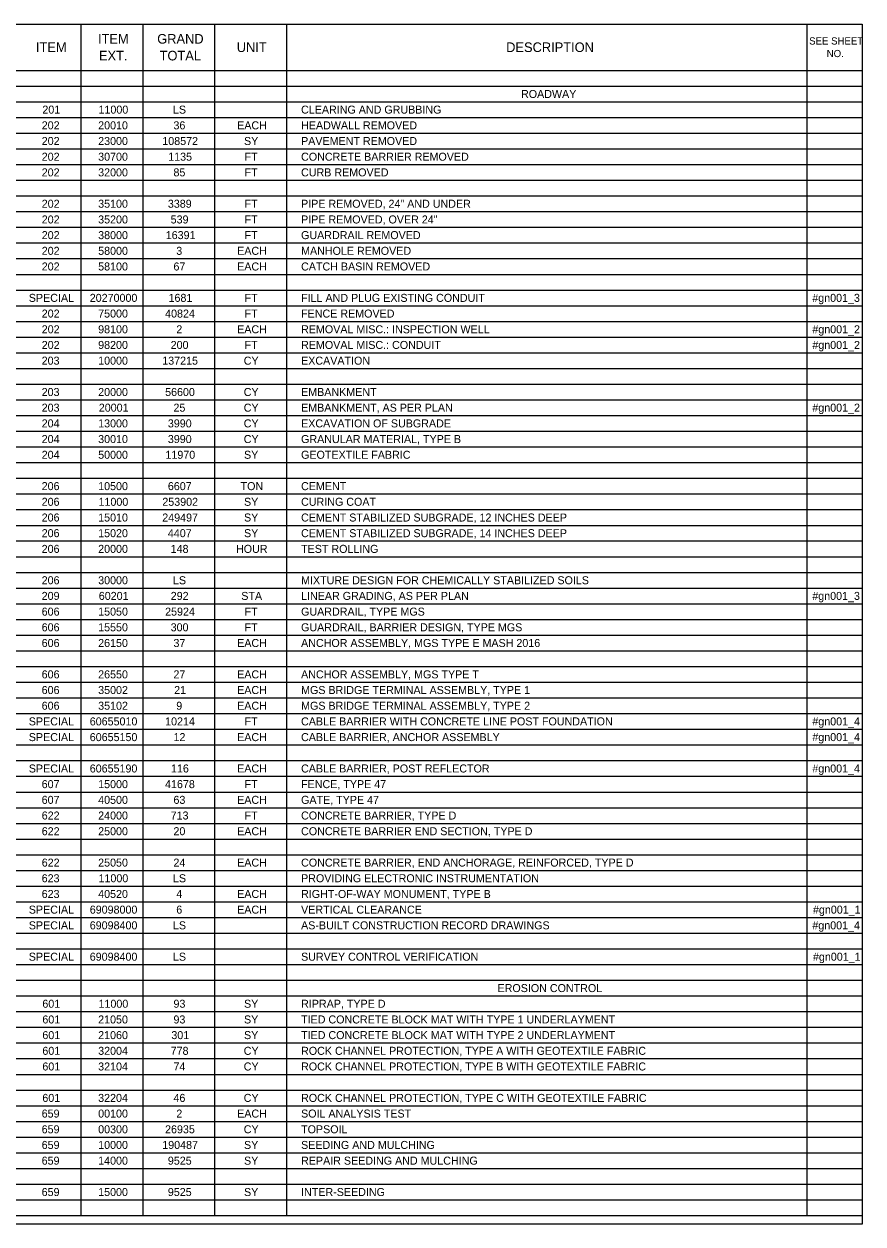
# Model space of a CAD drawing. Extents: x -542 to 295, y -281 to 32.
# Drawn here: x -400.52 to -385.84, y -10.59 to 10.41 of the extents above; entities that cross this region are included whole.
import ezdxf

# ---------------------------------------------------------------- set-up
doc = ezdxf.new("R2010")
doc.units = 0
for name, color, linetype in [('SC_Scratch1', 7, 'Continuous'), ('SH_Data', 7, 'Continuous'), ('SH_Text', 7, 'Continuous')]:
    doc.layers.add(name, color=color, linetype=linetype)

msp = doc.modelspace()

# ---------------------------------------------------------------- linework, layer by layer
at = {"layer": 'SC_Scratch1'}
msp.add_lwpolyline([(-416.359, 10.407), (-385.859, 10.407), (-385.859, -10.593), (-416.359, -10.593)], close=True, dxfattribs=at)
at = {"layer": 'SH_Data'}
for p, q in [((-416.359, 10.407), (-385.859, 10.407)), ((-399.523, 10.407), (-399.523, -10.444)), ((-398.437, 10.407), (-398.437, -10.444)), ((-397.182, 10.407), (-397.182, -10.444)), ((-395.926, 10.407), (-395.926, -10.444)), ((-386.827, 10.407), (-386.827, -10.444)), ((-385.859, 10.407), (-385.859, -10.444)), ((-416.359, 9.595), (-385.859, 9.595)), ((-416.359, 9.32), (-385.859, 9.32)), ((-416.359, 9.046), (-385.859, 9.046)), ((-416.359, 8.771), (-385.859, 8.771)), ((-416.359, 8.497), (-385.859, 8.497)), ((-416.359, 8.222), (-385.859, 8.222)), ((-416.359, 7.948), (-385.859, 7.948)), ((-416.359, 7.673), (-385.859, 7.673)), ((-416.359, 7.399), (-385.859, 7.399)), ((-416.359, 7.124), (-385.859, 7.124)), ((-416.359, 6.85), (-385.859, 6.85)), ((-416.359, 6.575), (-385.859, 6.575)), ((-416.359, 6.301), (-385.859, 6.301)), ((-416.359, 6.026), (-385.859, 6.026)), ((-416.359, 5.752), (-385.859, 5.752)), ((-416.359, 5.477), (-385.859, 5.477)), ((-416.359, 5.203), (-385.859, 5.203)), ((-416.359, 4.928), (-385.859, 4.928)), ((-416.359, 4.654), (-385.859, 4.654)), ((-416.359, 4.379), (-385.859, 4.379)), ((-416.359, 4.105), (-385.859, 4.105)), ((-416.359, 3.83), (-385.859, 3.83)), ((-416.359, 3.556), (-385.859, 3.556)), ((-416.359, 3.281), (-385.859, 3.281)), ((-416.359, 3.007), (-385.859, 3.007)), ((-416.359, 2.732), (-385.859, 2.732)), ((-416.359, 2.458), (-385.859, 2.458)), ((-416.359, 2.183), (-385.859, 2.183)), ((-416.359, 1.909), (-385.859, 1.909)), ((-416.359, 1.634), (-385.859, 1.634)), ((-416.359, 1.36), (-385.859, 1.36)), ((-416.359, 1.085), (-385.859, 1.085)), ((-416.359, 0.811), (-385.859, 0.811)), ((-416.359, 0.536), (-385.859, 0.536)), ((-416.359, 0.262), (-385.859, 0.262)), ((-416.359, -0.013), (-385.859, -0.013)), ((-416.359, -0.287), (-385.859, -0.287)), ((-416.359, -0.562), (-385.859, -0.562)), ((-416.359, -0.836), (-385.859, -0.836)), ((-416.359, -1.111), (-385.859, -1.111)), ((-416.359, -1.385), (-385.859, -1.385)), ((-416.359, -1.66), (-385.859, -1.66)), ((-416.359, -1.935), (-385.859, -1.935)), ((-416.359, -2.209), (-385.859, -2.209)), ((-416.359, -2.484), (-385.859, -2.484)), ((-416.359, -2.758), (-385.859, -2.758)), ((-416.359, -3.033), (-385.859, -3.033)), ((-416.359, -3.307), (-385.859, -3.307)), ((-416.359, -3.582), (-385.859, -3.582)), ((-416.359, -3.856), (-385.859, -3.856)), ((-416.359, -4.131), (-385.859, -4.131)), ((-416.359, -4.405), (-385.859, -4.405)), ((-416.359, -4.68), (-385.859, -4.68)), ((-416.359, -4.954), (-385.859, -4.954)), ((-416.359, -5.229), (-385.859, -5.229)), ((-416.359, -5.503), (-385.859, -5.503)), ((-416.359, -5.778), (-385.859, -5.778)), ((-416.359, -6.052), (-385.859, -6.052)), ((-416.359, -6.327), (-385.859, -6.327)), ((-416.359, -6.601), (-385.859, -6.601)), ((-416.359, -6.876), (-385.859, -6.876)), ((-416.359, -7.15), (-385.859, -7.15)), ((-416.359, -7.425), (-385.859, -7.425)), ((-416.359, -7.699), (-385.859, -7.699)), ((-416.359, -7.974), (-385.859, -7.974)), ((-416.359, -8.248), (-385.859, -8.248)), ((-416.359, -8.523), (-385.859, -8.523)), ((-416.359, -8.797), (-385.859, -8.797)), ((-416.359, -9.072), (-385.859, -9.072)), ((-416.359, -9.346), (-385.859, -9.346)), ((-416.359, -9.621), (-385.859, -9.621)), ((-416.359, -9.895), (-385.859, -9.895)), ((-416.359, -10.17), (-385.859, -10.17)), ((-416.359, -10.444), (-385.859, -10.444))]:
    msp.add_line(p, q, dxfattribs=at)

# ---------------------------------------------------------------- texts
at = {"layer": 'SH_Text'}
for s, height, p in [('ITEM', 0.168, (-400.307, 9.917)), ('ITEM', 0.168, (-399.222, 10.064)), ('GRAND ', 0.168, (-398.186, 10.064)), ('UNIT', 0.168, (-396.795, 9.917)), ('DESCRIPTION', 0.168, (-392.083, 9.917)), ('SEE SHEET ', 0.126, (-386.784, 10.048)), ('EXT.', 0.168, (-399.205, 9.77)), ('TOTAL', 0.168, (-398.144, 9.77)), ('NO.', 0.126, (-386.477, 9.828)), ('ROADWAY', 0.14, (-391.823, 9.113)), ('201', 0.14, (-400.195, 8.839)), ('11000', 0.14, (-399.213, 8.839)), ('LS', 0.14, (-397.911, 8.839)), ('CLEARING AND GRUBBING', 0.14, (-395.67, 8.839)), ('202', 0.14, (-400.206, 8.564)), ('20010', 0.14, (-399.219, 8.564)), ('36', 0.14, (-397.902, 8.564)), ('EACH', 0.14, (-396.788, 8.564)), ('HEADWALL REMOVED', 0.14, (-395.67, 8.564)), ('202', 0.14, (-400.206, 8.29)), ('23000', 0.14, (-399.219, 8.29)), ('108572', 0.14, (-398.097, 8.29)), ('SY', 0.14, (-396.668, 8.29)), ('PAVEMENT REMOVED', 0.14, (-395.67, 8.29)), ('202', 0.14, (-400.206, 8.015)), ('30700', 0.14, (-399.219, 8.015)), ('1135', 0.14, (-397.994, 8.015)), ('FT', 0.14, (-396.658, 8.015)), ('CONCRETE BARRIER REMOVED', 0.14, (-395.67, 8.015)), ('202', 0.14, (-400.206, 7.741)), ('32000', 0.14, (-399.219, 7.741)), ('85', 0.14, (-397.902, 7.741)), ('FT', 0.14, (-396.658, 7.741)), ('CURB REMOVED', 0.14, (-395.67, 7.741)), ('202', 0.14, (-400.206, 7.192)), ('35100', 0.14, (-399.219, 7.192)), ('3389', 0.14, (-398, 7.192)), ('FT', 0.14, (-396.658, 7.192)), ('PIPE REMOVED, 24" AND UNDER', 0.14, (-395.67, 7.192)), ('202', 0.14, (-400.206, 6.917)), ('35200', 0.14, (-399.219, 6.917)), ('539', 0.14, (-397.951, 6.917)), ('FT', 0.14, (-396.658, 6.917)), ('PIPE REMOVED, OVER 24"', 0.14, (-395.67, 6.917)), ('202', 0.14, (-400.206, 6.643)), ('38000', 0.14, (-399.219, 6.643)), ('16391', 0.14, (-398.037, 6.643)), ('FT', 0.14, (-396.658, 6.643)), ('GUARDRAIL REMOVED', 0.14, (-395.67, 6.643)), ('202', 0.14, (-400.206, 6.368)), ('58000', 0.14, (-399.219, 6.368)), ('3', 0.14, (-397.853, 6.368)), ('EACH', 0.14, (-396.788, 6.368)), ('MANHOLE REMOVED', 0.14, (-395.67, 6.368)), ('202', 0.14, (-400.206, 6.094)), ('58100', 0.14, (-399.219, 6.094)), ('67', 0.14, (-397.902, 6.094)), ('EACH', 0.14, (-396.788, 6.094)), ('CATCH BASIN REMOVED', 0.14, (-395.67, 6.094)), ('SPECIAL', 0.14, (-400.432, 5.545)), ('20270000', 0.14, (-399.366, 5.545)), ('1681', 0.14, (-397.988, 5.545)), ('FT', 0.14, (-396.658, 5.545)), ('FILL AND PLUG EXISTING CONDUIT', 0.14, (-395.67, 5.545)), ('#gn001_3', 0.14, (-386.729, 5.545)), ('202', 0.14, (-400.206, 5.27)), ('75000', 0.14, (-399.219, 5.27)), ('40824', 0.14, (-398.048, 5.27)), ('FT', 0.14, (-396.658, 5.27)), ('FENCE REMOVED', 0.14, (-395.67, 5.27)), ('202', 0.14, (-400.206, 4.995)), ('98100', 0.14, (-399.219, 4.995)), ('2', 0.14, (-397.852, 4.995)), ('EACH', 0.14, (-396.788, 4.995)), ('REMOVAL MISC.: INSPECTION WELL', 0.14, (-395.67, 4.995)), ('#gn001_2', 0.14, (-386.728, 4.995)), ('202', 0.14, (-400.206, 4.721)), ('98200', 0.14, (-399.219, 4.721)), ('200', 0.14, (-397.951, 4.721)), ('FT', 0.14, (-396.658, 4.721)), ('REMOVAL MISC.: CONDUIT', 0.14, (-395.67, 4.721)), ('#gn001_2', 0.14, (-386.728, 4.721)), ('203', 0.14, (-400.207, 4.446)), ('10000', 0.14, (-399.219, 4.446)), ('137215', 0.14, (-398.098, 4.446)), ('CY', 0.14, (-396.673, 4.446)), ('EXCAVATION', 0.14, (-395.67, 4.446)), ('203', 0.14, (-400.207, 3.897)), ('20000', 0.14, (-399.219, 3.897)), ('56600', 0.14, (-398.048, 3.897)), ('CY', 0.14, (-396.673, 3.897)), ('EMBANKMENT', 0.14, (-395.67, 3.897)), ('203', 0.14, (-400.207, 3.623)), ('20001', 0.14, (-399.208, 3.623)), ('25', 0.14, (-397.902, 3.623)), ('CY', 0.14, (-396.673, 3.623)), ('EMBANKMENT, AS PER PLAN', 0.14, (-395.67, 3.623)), ('#gn001_2', 0.14, (-386.728, 3.623)), ('204', 0.14, (-400.207, 3.348)), ('13000', 0.14, (-399.219, 3.348)), ('3990', 0.14, (-398, 3.348)), ('CY', 0.14, (-396.673, 3.348)), ('EXCAVATION OF SUBGRADE', 0.14, (-395.67, 3.348)), ('204', 0.14, (-400.207, 3.074)), ('30010', 0.14, (-399.219, 3.074)), ('3990', 0.14, (-398, 3.074)), ('CY', 0.14, (-396.673, 3.074)), ('GRANULAR MATERIAL, TYPE B', 0.14, (-395.67, 3.074)), ('204', 0.14, (-400.207, 2.799)), ('50000', 0.14, (-399.219, 2.799)), ('11970', 0.14, (-398.042, 2.799)), ('SY', 0.14, (-396.668, 2.799)), ('GEOTEXTILE FABRIC', 0.14, (-395.67, 2.799)), ('206', 0.14, (-400.207, 2.25)), ('10500', 0.14, (-399.219, 2.25)), ('6607', 0.14, (-398, 2.25)), ('TON', 0.14, (-396.728, 2.25)), ('CEMENT', 0.14, (-395.67, 2.25)), ('206', 0.14, (-400.207, 1.976)), ('11000', 0.14, (-399.213, 1.976)), ('253902', 0.14, (-398.097, 1.976)), ('SY', 0.14, (-396.668, 1.976)), ('CURING COAT', 0.14, (-395.67, 1.976)), ('206', 0.14, (-400.207, 1.701)), ('15010', 0.14, (-399.219, 1.701)), ('249497', 0.14, (-398.098, 1.701)), ('SY', 0.14, (-396.668, 1.701)), ('CEMENT STABILIZED SUBGRADE, 12 INCHES DEEP', 0.14, (-395.67, 1.701)), ('206', 0.14, (-400.207, 1.427)), ('15020', 0.14, (-399.219, 1.427)), ('4407', 0.14, (-398, 1.427)), ('SY', 0.14, (-396.668, 1.427)), ('CEMENT STABILIZED SUBGRADE, 14 INCHES DEEP', 0.14, (-395.67, 1.427)), ('206', 0.14, (-400.207, 1.152)), ('20000', 0.14, (-399.219, 1.152)), ('148', 0.14, (-397.951, 1.152)), ('HOUR', 0.14, (-396.808, 1.152)), ('TEST ROLLING', 0.14, (-395.67, 1.152)), ('206', 0.14, (-400.207, 0.603)), ('30000', 0.14, (-399.219, 0.603)), ('LS', 0.14, (-397.911, 0.603)), ('MIXTURE DESIGN FOR CHEMICALLY STABILIZED SOILS', 0.14, (-395.67, 0.603)), ('209', 0.14, (-400.207, 0.329)), ('60201', 0.14, (-399.208, 0.329)), ('292', 0.14, (-397.95, 0.329)), ('STA', 0.14, (-396.716, 0.329)), ('LINEAR GRADING, AS PER PLAN', 0.14, (-395.67, 0.329)), ('#gn001_3', 0.14, (-386.729, 0.329)), ('606', 0.14, (-400.207, 0.054)), ('15050', 0.14, (-399.219, 0.054)), ('25924', 0.14, (-398.048, 0.054)), ('FT', 0.14, (-396.658, 0.054)), ('GUARDRAIL, TYPE MGS', 0.14, (-395.67, 0.054)), ('606', 0.14, (-400.207, -0.22)), ('15550', 0.14, (-399.219, -0.22)), ('300', 0.14, (-397.951, -0.22)), ('FT', 0.14, (-396.658, -0.22)), ('GUARDRAIL, BARRIER DESIGN, TYPE MGS', 0.14, (-395.67, -0.22)), ('606', 0.14, (-400.207, -0.495)), ('26150', 0.14, (-399.219, -0.495)), ('37', 0.14, (-397.902, -0.495)), ('EACH', 0.14, (-396.788, -0.495)), ('ANCHOR ASSEMBLY, MGS TYPE E MASH 2016', 0.14, (-395.67, -0.495)), ('606', 0.14, (-400.207, -1.044)), ('26550', 0.14, (-399.219, -1.044)), ('27', 0.14, (-397.902, -1.044)), ('EACH', 0.14, (-396.788, -1.044)), ('ANCHOR ASSEMBLY, MGS TYPE T', 0.14, (-395.67, -1.044)), ('606', 0.14, (-400.207, -1.318)), ('35002', 0.14, (-399.219, -1.318)), ('21', 0.14, (-397.89, -1.318)), ('EACH', 0.14, (-396.788, -1.318)), ('MGS BRIDGE TERMINAL ASSEMBLY, TYPE 1', 0.14, (-395.67, -1.318)), ('606', 0.14, (-400.207, -1.593)), ('35102', 0.14, (-399.219, -1.593)), ('9', 0.14, (-397.853, -1.593)), ('EACH', 0.14, (-396.788, -1.593)), ('MGS BRIDGE TERMINAL ASSEMBLY, TYPE 2', 0.14, (-395.67, -1.593)), ('SPECIAL', 0.14, (-400.432, -1.867)), ('60655010', 0.14, (-399.366, -1.867)), ('10214', 0.14, (-398.048, -1.867)), ('FT', 0.14, (-396.658, -1.867)), ('CABLE BARRIER WITH CONCRETE LINE POST FOUNDATION', 0.14, (-395.67, -1.867)), ('#gn001_4', 0.14, (-386.728, -1.867)), ('SPECIAL', 0.14, (-400.432, -2.142)), ('60655150', 0.14, (-399.366, -2.142)), ('12', 0.14, (-397.901, -2.142)), ('EACH', 0.14, (-396.788, -2.142)), ('CABLE BARRIER, ANCHOR ASSEMBLY', 0.14, (-395.67, -2.142)), ('#gn001_4', 0.14, (-386.728, -2.142)), ('SPECIAL', 0.14, (-400.432, -2.691)), ('60655190', 0.14, (-399.366, -2.691)), ('116', 0.14, (-397.945, -2.691)), ('EACH', 0.14, (-396.788, -2.691)), ('CABLE BARRIER, POST REFLECTOR', 0.14, (-395.67, -2.691)), ('#gn001_4', 0.14, (-386.728, -2.691)), ('607', 0.14, (-400.207, -2.965)), ('15000', 0.14, (-399.219, -2.965)), ('41678', 0.14, (-398.049, -2.965)), ('FT', 0.14, (-396.658, -2.965)), ('FENCE, TYPE 47', 0.14, (-395.67, -2.965)), ('607', 0.14, (-400.207, -3.24)), ('40500', 0.14, (-399.219, -3.24)), ('63', 0.14, (-397.902, -3.24)), ('EACH', 0.14, (-396.788, -3.24)), ('GATE, TYPE 47', 0.14, (-395.67, -3.24)), ('622', 0.14, (-400.206, -3.514)), ('24000', 0.14, (-399.219, -3.514)), ('713', 0.14, (-397.951, -3.514)), ('FT', 0.14, (-396.658, -3.514)), ('CONCRETE BARRIER, TYPE D', 0.14, (-395.67, -3.514)), ('622', 0.14, (-400.206, -3.789)), ('25000', 0.14, (-399.219, -3.789)), ('20', 0.14, (-397.902, -3.789)), ('EACH', 0.14, (-396.788, -3.789)), ('CONCRETE BARRIER END SECTION, TYPE D', 0.14, (-395.67, -3.789)), ('622', 0.14, (-400.206, -4.338)), ('25050', 0.14, (-399.219, -4.338)), ('24', 0.14, (-397.902, -4.338)), ('EACH', 0.14, (-396.788, -4.338)), ('CONCRETE BARRIER, END ANCHORAGE, REINFORCED, TYPE D', 0.14, (-395.67, -4.338)), ('623', 0.14, (-400.207, -4.612)), ('11000', 0.14, (-399.213, -4.612)), ('LS', 0.14, (-397.911, -4.612)), ('PROVIDING ELECTRONIC INSTRUMENTATION', 0.14, (-395.67, -4.612)), ('623', 0.14, (-400.207, -4.887)), ('40520', 0.14, (-399.219, -4.887)), ('4', 0.14, (-397.853, -4.887)), ('EACH', 0.14, (-396.788, -4.887)), ('RIGHT-OF-WAY MONUMENT, TYPE B', 0.14, (-395.67, -4.887)), ('SPECIAL', 0.14, (-400.432, -5.161)), ('69098000', 0.14, (-399.366, -5.161)), ('6', 0.14, (-397.853, -5.161)), ('EACH', 0.14, (-396.788, -5.161)), ('VERTICAL CLEARANCE', 0.14, (-395.67, -5.161)), ('#gn001_1', 0.14, (-386.717, -5.161)), ('SPECIAL', 0.14, (-400.432, -5.436)), ('69098400', 0.14, (-399.366, -5.436)), ('LS', 0.14, (-397.911, -5.436)), ('AS-BUILT CONSTRUCTION RECORD DRAWINGS', 0.14, (-395.67, -5.436)), ('#gn001_4', 0.14, (-386.728, -5.436)), ('SPECIAL', 0.14, (-400.432, -5.985)), ('69098400', 0.14, (-399.366, -5.985)), ('LS', 0.14, (-397.911, -5.985)), ('SURVEY CONTROL VERIFICATION', 0.14, (-395.67, -5.985)), ('#gn001_1', 0.14, (-386.717, -5.985)), ('EROSION CONTROL', 0.14, (-392.234, -6.534)), ('601', 0.14, (-400.195, -6.808)), ('11000', 0.14, (-399.213, -6.808)), ('93', 0.14, (-397.902, -6.808)), ('SY', 0.14, (-396.668, -6.808)), ('RIPRAP, TYPE D', 0.14, (-395.67, -6.808)), ('601', 0.14, (-400.195, -7.083)), ('21050', 0.14, (-399.219, -7.083)), ('93', 0.14, (-397.902, -7.083)), ('SY', 0.14, (-396.668, -7.083)), ('TIED CONCRETE BLOCK MAT WITH TYPE 1 UNDERLAYMENT', 0.14, (-395.67, -7.083)), ('601', 0.14, (-400.195, -7.357)), ('21060', 0.14, (-399.219, -7.357)), ('301', 0.14, (-397.939, -7.357)), ('SY', 0.14, (-396.668, -7.357)), ('TIED CONCRETE BLOCK MAT WITH TYPE 2 UNDERLAYMENT', 0.14, (-395.67, -7.357)), ('601', 0.14, (-400.195, -7.632)), ('32004', 0.14, (-399.219, -7.632)), ('778', 0.14, (-397.951, -7.632)), ('CY', 0.14, (-396.673, -7.632)), ('ROCK CHANNEL PROTECTION, TYPE A WITH GEOTEXTILE FABRIC', 0.14, (-395.67, -7.632)), ('601', 0.14, (-400.195, -7.906)), ('32104', 0.14, (-399.219, -7.906)), ('74', 0.14, (-397.902, -7.906)), ('CY', 0.14, (-396.673, -7.906)), ('ROCK CHANNEL PROTECTION, TYPE B WITH GEOTEXTILE FABRIC', 0.14, (-395.67, -7.906)), ('601', 0.14, (-400.195, -8.456)), ('32204', 0.14, (-399.219, -8.456)), ('46', 0.14, (-397.902, -8.456)), ('CY', 0.14, (-396.673, -8.456)), ('ROCK CHANNEL PROTECTION, TYPE C WITH GEOTEXTILE FABRIC', 0.14, (-395.67, -8.456)), ('659', 0.14, (-400.207, -8.73)), ('00100', 0.14, (-399.219, -8.73)), ('2', 0.14, (-397.852, -8.73)), ('EACH', 0.14, (-396.788, -8.73)), ('SOIL ANALYSIS TEST', 0.14, (-395.67, -8.73)), ('659', 0.14, (-400.207, -9.005)), ('00300', 0.14, (-399.219, -9.005)), ('26935', 0.14, (-398.049, -9.005)), ('CY', 0.14, (-396.673, -9.005)), ('TOPSOIL', 0.14, (-395.67, -9.005)), ('659', 0.14, (-400.207, -9.279)), ('10000', 0.14, (-399.219, -9.279)), ('190487', 0.14, (-398.098, -9.279)), ('SY', 0.14, (-396.668, -9.279)), ('SEEDING AND MULCHING', 0.14, (-395.67, -9.279)), ('659', 0.14, (-400.207, -9.554)), ('14000', 0.14, (-399.219, -9.554)), ('9525', 0.14, (-398, -9.554)), ('SY', 0.14, (-396.668, -9.554)), ('REPAIR SEEDING AND MULCHING', 0.14, (-395.67, -9.554)), ('659', 0.14, (-400.207, -10.103)), ('15000', 0.14, (-399.219, -10.103)), ('9525', 0.14, (-398, -10.103)), ('SY', 0.14, (-396.668, -10.103)), ('INTER-SEEDING', 0.14, (-395.67, -10.103))]:
    msp.add_text(s, height=height, dxfattribs=at).set_placement(p)

doc.saveas('drawing.dxf')
